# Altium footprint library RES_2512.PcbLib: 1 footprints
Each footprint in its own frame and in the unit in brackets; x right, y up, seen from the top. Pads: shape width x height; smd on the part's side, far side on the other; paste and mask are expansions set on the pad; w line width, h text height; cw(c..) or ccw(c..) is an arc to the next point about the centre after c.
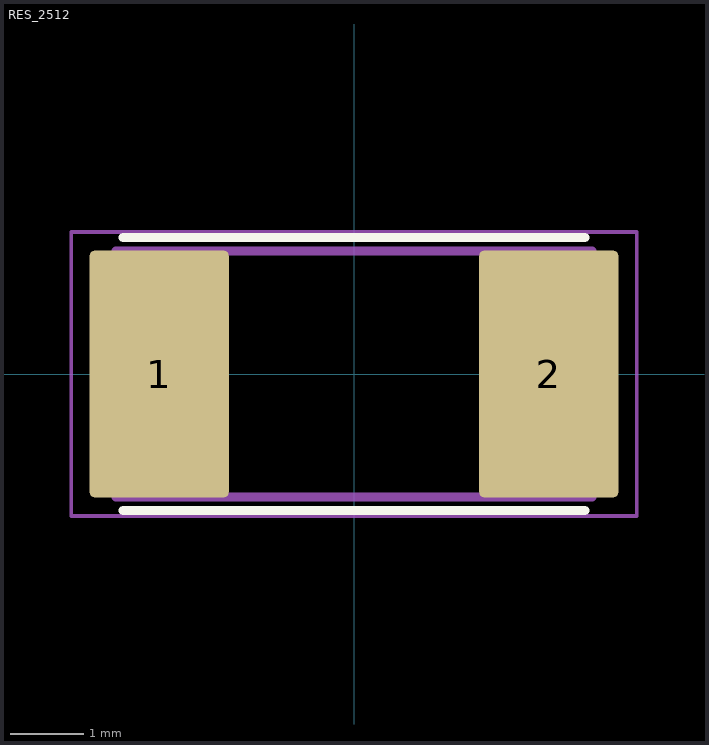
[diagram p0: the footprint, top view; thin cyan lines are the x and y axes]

## RES_2512 [mm]
pads (2):
  rrect7% 1.9x3.37 smd: 1(-2.66,0) 2(2.66,0)
Top Overlay:
  lines w0.127: -3.15,-1.865 3.15,-1.865 ; -3.15,1.865 3.15,1.865
Mechanical 13:
  lines w0.127: -3.25,-1.68 -3.25,1.68 3.25,1.68 3.25,-1.68 -3.25,-1.68
Mechanical 15:
  lines w0.05: -3.86,-1.94 -3.86,1.94 3.86,1.94 3.86,-1.94 -3.86,-1.94
3D body "RES_2512.STEP": height 0, standoff -0.65, extent -3.175,-1.6 3.175,1.6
